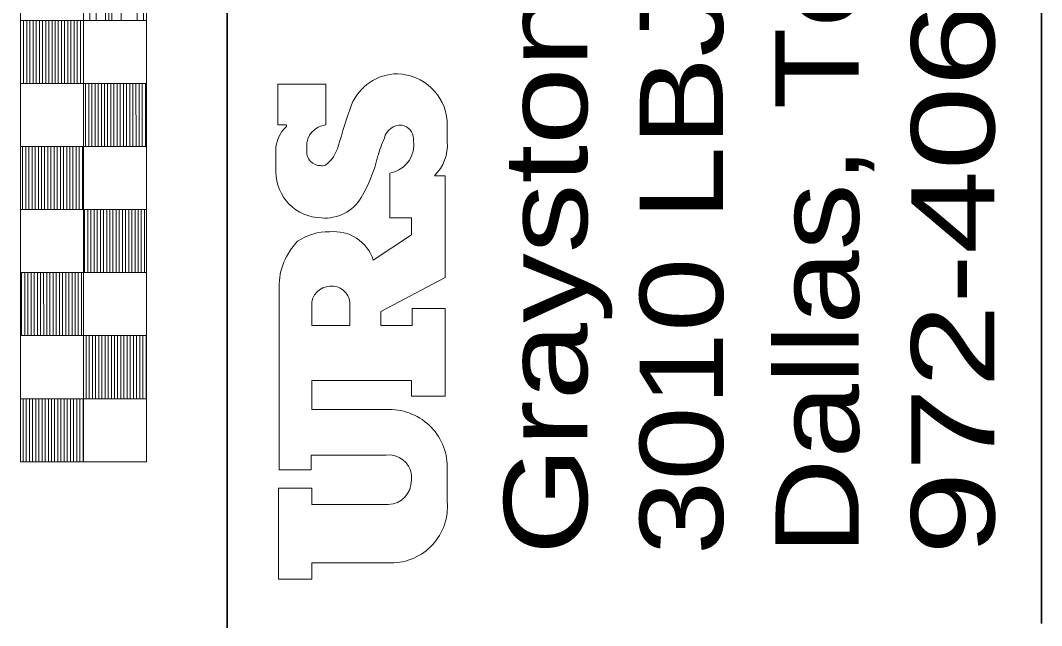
# Model space of a CAD drawing. Extents: x 2363323 to 2367082, y 6956018 to 6980837.
# Drawn here: x 2366568.7 to 2366730.8, y 6979505.4 to 6979601.4 of the extents above; entities that cross this region are included whole.
import ezdxf

# ---------------------------------------------------------------- set-up
doc = ezdxf.new("R2010")
doc.units = 0
doc.header["$LTSCALE"] = 4.1
doc.layers.add('62', color=7, linetype='Continuous', lineweight=13)
doc.layers.add('63', color=7, linetype='Continuous', lineweight=13)

msp = doc.modelspace()

# ---------------------------------------------------------------- linework, layer by layer
at = {"layer": '62', "lineweight": 35}
for p, q in [((2366601.526, 6980156.078), (2366601.527, 6979505.057)), ((2366730.792, 6979899.251), (2366730.792, 6979505.756))]:
    msp.add_line(p, q, dxfattribs=at)
at = {"layer": '62'}
for p, q in [((2366568.707, 6979531.397), (2366568.707, 6979931.434)), ((2366578.708, 6979531.398), (2366578.708, 6979931.434)), ((2366588.708, 6979531.397), (2366588.709, 6979931.434)), ((2366578.719, 6979601.403), (2366578.719, 6979611.405)), ((2366579.719, 6979601.403), (2366579.719, 6979611.406)), ((2366580.719, 6979601.403), (2366580.719, 6979611.405)), ((2366582.219, 6979601.403), (2366582.219, 6979611.406)), ((2366582.719, 6979601.403), (2366582.719, 6979611.405)), ((2366583.219, 6979601.403), (2366583.219, 6979611.405)), ((2366584.719, 6979601.403), (2366584.719, 6979611.406)), ((2366587.219, 6979601.403), (2366587.22, 6979611.406)), ((2366588.22, 6979601.403), (2366588.22, 6979611.405)), ((2366568.719, 6979591.402), (2366568.718, 6979601.404)), ((2366569.219, 6979591.402), (2366569.219, 6979601.404)), ((2366569.721, 6979591.402), (2366569.72, 6979601.403)), ((2366570.221, 6979591.403), (2366570.219, 6979601.403)), ((2366570.72, 6979591.402), (2366570.72, 6979601.403)), ((2366571.22, 6979591.402), (2366571.22, 6979601.404)), ((2366571.719, 6979591.403), (2366571.72, 6979601.403)), ((2366572.22, 6979591.402), (2366572.22, 6979601.403)), ((2366572.72, 6979591.403), (2366572.72, 6979601.404)), ((2366573.22, 6979591.403), (2366573.22, 6979601.403)), ((2366573.72, 6979591.402), (2366573.72, 6979601.404)), ((2366574.219, 6979591.402), (2366574.221, 6979601.404)), ((2366574.72, 6979591.402), (2366574.72, 6979601.403)), ((2366575.22, 6979591.403), (2366575.22, 6979601.403)), ((2366575.72, 6979591.402), (2366575.72, 6979601.403)), ((2366576.22, 6979591.402), (2366576.22, 6979601.404)), ((2366576.72, 6979591.403), (2366576.72, 6979601.403)), ((2366577.22, 6979591.402), (2366577.22, 6979601.403)), ((2366577.72, 6979591.403), (2366577.72, 6979601.404)), ((2366578.22, 6979591.403), (2366578.22, 6979601.403)), ((2366578.707, 6979601.403), (2366588.709, 6979601.404)), ((2366568.707, 6979591.402), (2366578.707, 6979591.402)), ((2366579.05, 6979581.402), (2366579.051, 6979591.403)), ((2366579.551, 6979581.401), (2366579.551, 6979591.403)), ((2366580.05, 6979581.401), (2366580.051, 6979591.404)), ((2366580.55, 6979581.402), (2366580.551, 6979591.403)), ((2366581.051, 6979581.401), (2366581.051, 6979591.404)), ((2366581.55, 6979581.401), (2366581.552, 6979591.403)), ((2366582.051, 6979581.401), (2366582.051, 6979591.402)), ((2366582.551, 6979581.401), (2366582.551, 6979591.403)), ((2366583.05, 6979581.401), (2366583.051, 6979591.403)), ((2366583.551, 6979581.401), (2366583.551, 6979591.403)), ((2366584.051, 6979581.402), (2366584.052, 6979591.403)), ((2366584.551, 6979581.401), (2366584.55, 6979591.403)), ((2366585.051, 6979581.402), (2366585.05, 6979591.404)), ((2366585.551, 6979581.4), (2366585.55, 6979591.403)), ((2366586.052, 6979581.4), (2366586.051, 6979591.403)), ((2366586.552, 6979581.401), (2366586.552, 6979591.403)), ((2366587.052, 6979581.401), (2366587.051, 6979591.403)), ((2366587.552, 6979581.401), (2366587.551, 6979591.404)), ((2366588.053, 6979581.401), (2366588.052, 6979591.403)), ((2366588.552, 6979581.401), (2366588.552, 6979591.404)), ((2366636.462, 6979585.477), (2366636.462, 6979582.143)), ((2366631.133, 6979581.436), (2366631.093, 6979582.636)), ((2366568.706, 6979581.402), (2366578.708, 6979581.401)), ((2366569.049, 6979571.4), (2366569.051, 6979581.401)), ((2366569.55, 6979571.4), (2366569.55, 6979581.401)), ((2366570.051, 6979571.4), (2366570.051, 6979581.401)), ((2366570.551, 6979571.401), (2366570.552, 6979581.401)), ((2366571.051, 6979571.4), (2366571.05, 6979581.401)), ((2366571.551, 6979571.401), (2366571.55, 6979581.402)), ((2366572.051, 6979571.4), (2366572.051, 6979581.402)), ((2366572.551, 6979571.4), (2366572.551, 6979581.402)), ((2366573.051, 6979571.401), (2366573.051, 6979581.402)), ((2366573.551, 6979571.401), (2366573.55, 6979581.401)), ((2366574.051, 6979571.4), (2366574.05, 6979581.402)), ((2366574.551, 6979571.4), (2366574.551, 6979581.401)), ((2366575.051, 6979571.4), (2366575.051, 6979581.402)), ((2366575.551, 6979571.401), (2366575.551, 6979581.401)), ((2366576.051, 6979571.4), (2366576.051, 6979581.401)), ((2366576.551, 6979571.401), (2366576.551, 6979581.402)), ((2366577.051, 6979571.401), (2366577.051, 6979581.402)), ((2366577.55, 6979571.4), (2366577.55, 6979581.401)), ((2366578.05, 6979571.401), (2366578.051, 6979581.401)), ((2366578.55, 6979571.4), (2366578.55, 6979581.401)), ((2366578.707, 6979581.402), (2366588.708, 6979581.401)), ((2366578.708, 6979581.401), (2366588.709, 6979581.402)), ((2366609.239, 6979577.41), (2366609.239, 6979580.744)), ((2366614.165, 6979581.323), (2366614.165, 6979580.638)), ((2366568.707, 6979571.4), (2366578.708, 6979571.4)), ((2366578.895, 6979561.4), (2366578.896, 6979571.4)), ((2366579.395, 6979561.4), (2366579.396, 6979571.4)), ((2366579.896, 6979561.4), (2366579.895, 6979571.4)), ((2366580.395, 6979561.4), (2366580.396, 6979571.4)), ((2366580.896, 6979561.4), (2366580.896, 6979571.4)), ((2366581.396, 6979561.4), (2366581.396, 6979571.4)), ((2366581.895, 6979561.4), (2366581.896, 6979571.4)), ((2366582.396, 6979561.4), (2366582.396, 6979571.4)), ((2366582.895, 6979561.4), (2366582.897, 6979571.401)), ((2366583.396, 6979561.4), (2366583.395, 6979571.4)), ((2366583.896, 6979561.4), (2366583.895, 6979571.4)), ((2366584.396, 6979561.401), (2366584.395, 6979571.4)), ((2366584.896, 6979561.4), (2366584.895, 6979571.4)), ((2366585.396, 6979561.4), (2366585.396, 6979571.401)), ((2366585.897, 6979561.401), (2366585.896, 6979571.401)), ((2366586.396, 6979561.4), (2366586.397, 6979571.4)), ((2366586.896, 6979561.401), (2366586.896, 6979571.4)), ((2366587.396, 6979561.4), (2366587.396, 6979571.4)), ((2366587.896, 6979561.4), (2366587.897, 6979571.4)), ((2366588.397, 6979561.4), (2366588.396, 6979571.4)), ((2366568.706, 6979561.4), (2366578.707, 6979561.401)), ((2366568.895, 6979551.4), (2366568.895, 6979561.401)), ((2366569.395, 6979551.4), (2366569.395, 6979561.4)), ((2366569.897, 6979551.4), (2366569.895, 6979561.401)), ((2366570.396, 6979551.4), (2366570.396, 6979561.4)), ((2366570.897, 6979551.399), (2366570.895, 6979561.4)), ((2366571.396, 6979551.399), (2366571.395, 6979561.4)), ((2366571.896, 6979551.399), (2366571.896, 6979561.401)), ((2366572.396, 6979551.4), (2366572.395, 6979561.401)), ((2366572.895, 6979551.4), (2366572.896, 6979561.4)), ((2366573.395, 6979551.4), (2366573.396, 6979561.401)), ((2366573.896, 6979551.4), (2366573.895, 6979561.401)), ((2366574.395, 6979551.4), (2366574.396, 6979561.401)), ((2366574.896, 6979551.399), (2366574.896, 6979561.401)), ((2366575.395, 6979551.399), (2366575.396, 6979561.4)), ((2366575.895, 6979551.4), (2366575.896, 6979561.4)), ((2366576.396, 6979551.399), (2366576.396, 6979561.4)), ((2366576.895, 6979551.399), (2366576.896, 6979561.401)), ((2366577.396, 6979551.4), (2366577.396, 6979561.4)), ((2366577.896, 6979551.4), (2366577.896, 6979561.4)), ((2366578.396, 6979551.4), (2366578.396, 6979561.401)), ((2366578.707, 6979561.4), (2366588.709, 6979561.4)), ((2366578.708, 6979561.398), (2366588.709, 6979561.398)), ((2366614.942, 6979552.995), (2366614.942, 6979556.76)), ((2366568.707, 6979551.399), (2366578.707, 6979551.399)), ((2366579.14, 6979541.398), (2366579.14, 6979551.398)), ((2366579.64, 6979541.398), (2366579.64, 6979551.397)), ((2366580.14, 6979541.398), (2366580.141, 6979551.398)), ((2366580.64, 6979541.398), (2366580.64, 6979551.398)), ((2366581.14, 6979541.398), (2366581.14, 6979551.399)), ((2366581.64, 6979541.399), (2366581.641, 6979551.398)), ((2366582.14, 6979541.397), (2366582.14, 6979551.398)), ((2366582.64, 6979541.398), (2366582.641, 6979551.397)), ((2366583.14, 6979541.398), (2366583.14, 6979551.397)), ((2366583.64, 6979541.397), (2366583.64, 6979551.398)), ((2366584.14, 6979541.398), (2366584.141, 6979551.398)), ((2366584.641, 6979541.398), (2366584.64, 6979551.397)), ((2366585.141, 6979541.398), (2366585.141, 6979551.398)), ((2366585.642, 6979541.398), (2366585.642, 6979551.398)), ((2366586.141, 6979541.397), (2366586.142, 6979551.399)), ((2366586.641, 6979541.398), (2366586.642, 6979551.397)), ((2366587.142, 6979541.397), (2366587.142, 6979551.398)), ((2366587.642, 6979541.398), (2366587.641, 6979551.398)), ((2366588.142, 6979541.397), (2366588.141, 6979551.398)), ((2366588.642, 6979541.397), (2366588.641, 6979551.399)), ((2366568.708, 6979541.398), (2366578.708, 6979541.398)), ((2366569.138, 6979531.397), (2366569.14, 6979541.399)), ((2366569.64, 6979531.398), (2366569.64, 6979541.399)), ((2366570.14, 6979531.397), (2366570.14, 6979541.399)), ((2366570.64, 6979531.398), (2366570.64, 6979541.398)), ((2366571.14, 6979531.397), (2366571.14, 6979541.398)), ((2366571.64, 6979531.398), (2366571.64, 6979541.398)), ((2366572.14, 6979531.397), (2366572.14, 6979541.398)), ((2366572.64, 6979531.397), (2366572.64, 6979541.399)), ((2366573.14, 6979531.398), (2366573.14, 6979541.398)), ((2366573.64, 6979531.397), (2366573.64, 6979541.398)), ((2366574.14, 6979531.397), (2366574.14, 6979541.398)), ((2366574.64, 6979531.397), (2366574.639, 6979541.398)), ((2366575.14, 6979531.397), (2366575.139, 6979541.399)), ((2366575.64, 6979531.398), (2366575.639, 6979541.398)), ((2366576.14, 6979531.397), (2366576.139, 6979541.399)), ((2366576.64, 6979531.398), (2366576.64, 6979541.399)), ((2366577.14, 6979531.398), (2366577.139, 6979541.399)), ((2366577.639, 6979531.397), (2366577.64, 6979541.399)), ((2366578.139, 6979531.397), (2366578.139, 6979541.398)), ((2366578.639, 6979531.397), (2366578.639, 6979541.399)), ((2366578.708, 6979541.398), (2366588.709, 6979541.398)), ((2366568.707, 6979531.397), (2366578.708, 6979531.398)), ((2366636.466, 6979530.582), (2366636.462, 6979525.031)), ((2366630.759, 6979528.473), (2366630.759, 6979529.333))]:
    msp.add_line(p, q, dxfattribs=at)
for points in [[(2366588.71, 6979591.403), (2366588.709, 6979601.404), (2366568.707, 6979601.404), (2366568.707, 6979591.402)], [(2366588.709, 6979571.401), (2366588.709, 6979581.402), (2366568.706, 6979581.402), (2366568.707, 6979571.4)], [(2366588.709, 6979551.399), (2366588.709, 6979561.4), (2366568.706, 6979561.4), (2366568.707, 6979551.399)], [(2366588.708, 6979531.397), (2366588.709, 6979541.398), (2366568.708, 6979541.398), (2366568.707, 6979531.397)]]:
    msp.add_lwpolyline(points, close=True, dxfattribs=at)
for points in [[(2366610.926, 6979584.59), (2366610.926, 6979584.832), (2366609.561, 6979584.832), (2366609.561, 6979591.285), (2366617.201, 6979591.285), (2366617.201, 6979584.832)], [(2366624.713, 6979563.379), (2366630.759, 6979567.408), (2366630.759, 6979570.096), (2366627.316, 6979570.096), (2366627.316, 6979577.195)], [(2366634.418, 6979576.765), (2366636.14, 6979576.765), (2366636.14, 6979560.632), (2366625.917, 6979555.254), (2366625.917, 6979552.995), (2366630.867, 6979552.995), (2366630.867, 6979555.684), (2366636.14, 6979555.684), (2366636.14, 6979541.809), (2366630.759, 6979541.809), (2366630.759, 6979544.283), (2366614.942, 6979544.283), (2366614.942, 6979539.658), (2366626.778, 6979539.658)], [(2366626.778, 6979532.452), (2366614.834, 6979532.452), (2366614.834, 6979530.086), (2366609.777, 6979530.086), (2366609.777, 6979559.126)], [(2366620.967, 6979556.114), (2366620.967, 6979552.995), (2366614.942, 6979552.995)], [(2366627.531, 6979515.351), (2366614.942, 6979515.351), (2366614.942, 6979512.769), (2366609.669, 6979512.769), (2366609.669, 6979527.182), (2366614.942, 6979527.182), (2366614.942, 6979524.601), (2366627.101, 6979524.601)]]:
    msp.add_lwpolyline(points, dxfattribs=at)
for centre, radius, start, end in [((2366628.637, 6979584.927), 8.011, 90.4748, 157.35647), ((2366628.279, 6979584.726), 8.217, 5.23994, 87.97211), ((2366787.718, 6979531.062), 175.947, 161.11463, 163.35109), ((2366614.436, 6979580.757), 5.197, 132.47521, 180.13887), ((2366617.49, 6979581.513), 3.331, 94.97622, 183.26328), ((2366629.068, 6979582.123), 2.67, 86.42761, 166.58817), ((2366628.848, 6979582.575), 2.246, 1.56527, 80.09036), ((2366651.95, 6979571.919), 27.683, 156.98519, 163.48674), ((2366629.671, 6979581.647), 6.809, 314.19553, 4.1738), ((2366616.33, 6979580.533), 2.168, 177.22466, 270.15025), ((2366613.919, 6979582.788), 5.391, 306.33025, 345.86761), ((2366626.654, 6979581.629), 4.484, 278.49107, 357.52171), ((2366603.504, 6979584.874), 22.488, 329.02736, 346.92656), ((2366616.608, 6979577.452), 7.37, 180.32724, 269.1529), ((2366616.559, 6979580.015), 1.665, 262.3102, 289.43935), ((2366617.121, 6979576.617), 6.564, 264.56461, 329.65547), ((2366617.465, 6979559.565), 8.298, 87.96198, 124.96984), ((2366618.527, 6979561.413), 6.491, 17.63424, 96.78306), ((2366619.969, 6979559.211), 10.193, 135.41811, 180.47644), ((2366617.98, 6979556.159), 3.097, 81.97357, 168.82266), ((2366618.149, 6979556.405), 2.833, 354.11318, 84.67155), ((2366627.315, 6979530.523), 9.151, 0.37291, 93.36394), ((2366627.197, 6979528.886), 3.591, 7.15138, 96.69605), ((2366626.953, 6979528.405), 3.807, 272.2293, 1.01817), ((2366627.54, 6979524.303), 8.952, 269.94292, 4.66557)]:
    msp.add_arc(centre, radius, start, end, dxfattribs=at)
at = {"layer": '63'}
for p, q in [((2366568.707, 6979531.397), (2366568.707, 6979931.434)), ((2366578.708, 6979531.398), (2366578.708, 6979931.434)), ((2366588.708, 6979531.397), (2366588.709, 6979931.434)), ((2366578.719, 6979601.403), (2366578.719, 6979611.405)), ((2366579.719, 6979601.403), (2366579.719, 6979611.406)), ((2366580.719, 6979601.403), (2366580.719, 6979611.405)), ((2366582.219, 6979601.403), (2366582.219, 6979611.406)), ((2366582.719, 6979601.403), (2366582.719, 6979611.405)), ((2366583.219, 6979601.403), (2366583.219, 6979611.405)), ((2366584.719, 6979601.403), (2366584.719, 6979611.406)), ((2366587.219, 6979601.403), (2366587.22, 6979611.406)), ((2366588.22, 6979601.403), (2366588.22, 6979611.405)), ((2366568.719, 6979591.402), (2366568.718, 6979601.404)), ((2366569.219, 6979591.402), (2366569.219, 6979601.404)), ((2366569.721, 6979591.402), (2366569.72, 6979601.403)), ((2366570.221, 6979591.403), (2366570.219, 6979601.403)), ((2366570.72, 6979591.402), (2366570.72, 6979601.403)), ((2366571.22, 6979591.402), (2366571.22, 6979601.404)), ((2366571.719, 6979591.403), (2366571.72, 6979601.403)), ((2366572.22, 6979591.402), (2366572.22, 6979601.403)), ((2366572.72, 6979591.403), (2366572.72, 6979601.404)), ((2366573.22, 6979591.403), (2366573.22, 6979601.403)), ((2366573.72, 6979591.402), (2366573.72, 6979601.404)), ((2366574.219, 6979591.402), (2366574.221, 6979601.404)), ((2366574.72, 6979591.402), (2366574.72, 6979601.403)), ((2366575.22, 6979591.403), (2366575.22, 6979601.403)), ((2366575.72, 6979591.402), (2366575.72, 6979601.403)), ((2366576.22, 6979591.402), (2366576.22, 6979601.404)), ((2366576.72, 6979591.403), (2366576.72, 6979601.403)), ((2366577.22, 6979591.402), (2366577.22, 6979601.403)), ((2366577.72, 6979591.403), (2366577.72, 6979601.404)), ((2366578.22, 6979591.403), (2366578.22, 6979601.403)), ((2366578.707, 6979601.403), (2366588.709, 6979601.404)), ((2366568.707, 6979591.402), (2366578.707, 6979591.402)), ((2366579.05, 6979581.402), (2366579.051, 6979591.403)), ((2366579.551, 6979581.401), (2366579.551, 6979591.403)), ((2366580.05, 6979581.401), (2366580.051, 6979591.404)), ((2366580.55, 6979581.402), (2366580.551, 6979591.403)), ((2366581.051, 6979581.401), (2366581.051, 6979591.404)), ((2366581.55, 6979581.401), (2366581.552, 6979591.403)), ((2366582.051, 6979581.401), (2366582.051, 6979591.402)), ((2366582.551, 6979581.401), (2366582.551, 6979591.403)), ((2366583.05, 6979581.401), (2366583.051, 6979591.403)), ((2366583.551, 6979581.401), (2366583.551, 6979591.403)), ((2366584.051, 6979581.402), (2366584.052, 6979591.403)), ((2366584.551, 6979581.401), (2366584.55, 6979591.403)), ((2366585.051, 6979581.402), (2366585.05, 6979591.404)), ((2366585.551, 6979581.4), (2366585.55, 6979591.403)), ((2366586.052, 6979581.4), (2366586.051, 6979591.403)), ((2366586.552, 6979581.401), (2366586.552, 6979591.403)), ((2366587.052, 6979581.401), (2366587.051, 6979591.403)), ((2366587.552, 6979581.401), (2366587.551, 6979591.404)), ((2366588.053, 6979581.401), (2366588.052, 6979591.403)), ((2366588.552, 6979581.401), (2366588.552, 6979591.404)), ((2366568.706, 6979581.402), (2366578.708, 6979581.401)), ((2366569.049, 6979571.4), (2366569.051, 6979581.401)), ((2366569.55, 6979571.4), (2366569.55, 6979581.401)), ((2366570.051, 6979571.4), (2366570.051, 6979581.401)), ((2366570.551, 6979571.401), (2366570.552, 6979581.401)), ((2366571.051, 6979571.4), (2366571.05, 6979581.401)), ((2366571.551, 6979571.401), (2366571.55, 6979581.402)), ((2366572.051, 6979571.4), (2366572.051, 6979581.402)), ((2366572.551, 6979571.4), (2366572.551, 6979581.402)), ((2366573.051, 6979571.401), (2366573.051, 6979581.402)), ((2366573.551, 6979571.401), (2366573.55, 6979581.401)), ((2366574.051, 6979571.4), (2366574.05, 6979581.402)), ((2366574.551, 6979571.4), (2366574.551, 6979581.401)), ((2366575.051, 6979571.4), (2366575.051, 6979581.402)), ((2366575.551, 6979571.401), (2366575.551, 6979581.401)), ((2366576.051, 6979571.4), (2366576.051, 6979581.401)), ((2366576.551, 6979571.401), (2366576.551, 6979581.402)), ((2366577.051, 6979571.401), (2366577.051, 6979581.402)), ((2366577.55, 6979571.4), (2366577.55, 6979581.401)), ((2366578.05, 6979571.401), (2366578.051, 6979581.401)), ((2366578.55, 6979571.4), (2366578.55, 6979581.401)), ((2366578.707, 6979581.402), (2366588.708, 6979581.401)), ((2366578.708, 6979581.401), (2366588.709, 6979581.402)), ((2366568.707, 6979571.4), (2366578.708, 6979571.4)), ((2366578.895, 6979561.4), (2366578.896, 6979571.4)), ((2366579.395, 6979561.4), (2366579.396, 6979571.4)), ((2366579.896, 6979561.4), (2366579.895, 6979571.4)), ((2366580.395, 6979561.4), (2366580.396, 6979571.4)), ((2366580.896, 6979561.4), (2366580.896, 6979571.4)), ((2366581.396, 6979561.4), (2366581.396, 6979571.4)), ((2366581.895, 6979561.4), (2366581.896, 6979571.4)), ((2366582.396, 6979561.4), (2366582.396, 6979571.4)), ((2366582.895, 6979561.4), (2366582.897, 6979571.401)), ((2366583.396, 6979561.4), (2366583.395, 6979571.4)), ((2366583.896, 6979561.4), (2366583.895, 6979571.4)), ((2366584.396, 6979561.401), (2366584.395, 6979571.4)), ((2366584.896, 6979561.4), (2366584.895, 6979571.4)), ((2366585.396, 6979561.4), (2366585.396, 6979571.401)), ((2366585.897, 6979561.401), (2366585.896, 6979571.401)), ((2366586.396, 6979561.4), (2366586.397, 6979571.4)), ((2366586.896, 6979561.401), (2366586.896, 6979571.4)), ((2366587.396, 6979561.4), (2366587.396, 6979571.4)), ((2366587.896, 6979561.4), (2366587.897, 6979571.4)), ((2366588.397, 6979561.4), (2366588.396, 6979571.4)), ((2366568.706, 6979561.4), (2366578.707, 6979561.401)), ((2366568.895, 6979551.4), (2366568.895, 6979561.401)), ((2366569.395, 6979551.4), (2366569.395, 6979561.4)), ((2366569.897, 6979551.4), (2366569.895, 6979561.401)), ((2366570.396, 6979551.4), (2366570.396, 6979561.4)), ((2366570.897, 6979551.399), (2366570.895, 6979561.4)), ((2366571.396, 6979551.399), (2366571.395, 6979561.4)), ((2366571.896, 6979551.399), (2366571.896, 6979561.401)), ((2366572.396, 6979551.4), (2366572.395, 6979561.401)), ((2366572.895, 6979551.4), (2366572.896, 6979561.4)), ((2366573.395, 6979551.4), (2366573.396, 6979561.401)), ((2366573.896, 6979551.4), (2366573.895, 6979561.401)), ((2366574.395, 6979551.4), (2366574.396, 6979561.401)), ((2366574.896, 6979551.399), (2366574.896, 6979561.401)), ((2366575.395, 6979551.399), (2366575.396, 6979561.4)), ((2366575.895, 6979551.4), (2366575.896, 6979561.4)), ((2366576.396, 6979551.399), (2366576.396, 6979561.4)), ((2366576.895, 6979551.399), (2366576.896, 6979561.401)), ((2366577.396, 6979551.4), (2366577.396, 6979561.4)), ((2366577.896, 6979551.4), (2366577.896, 6979561.4)), ((2366578.396, 6979551.4), (2366578.396, 6979561.401)), ((2366578.707, 6979561.4), (2366588.709, 6979561.4)), ((2366578.708, 6979561.398), (2366588.709, 6979561.398)), ((2366568.707, 6979551.399), (2366578.707, 6979551.399)), ((2366579.14, 6979541.398), (2366579.14, 6979551.398)), ((2366579.64, 6979541.398), (2366579.64, 6979551.397)), ((2366580.14, 6979541.398), (2366580.141, 6979551.398)), ((2366580.64, 6979541.398), (2366580.64, 6979551.398)), ((2366581.14, 6979541.398), (2366581.14, 6979551.399)), ((2366581.64, 6979541.399), (2366581.641, 6979551.398)), ((2366582.14, 6979541.397), (2366582.14, 6979551.398)), ((2366582.64, 6979541.398), (2366582.641, 6979551.397)), ((2366583.14, 6979541.398), (2366583.14, 6979551.397)), ((2366583.64, 6979541.397), (2366583.64, 6979551.398)), ((2366584.14, 6979541.398), (2366584.141, 6979551.398)), ((2366584.641, 6979541.398), (2366584.64, 6979551.397)), ((2366585.141, 6979541.398), (2366585.141, 6979551.398)), ((2366585.642, 6979541.398), (2366585.642, 6979551.398)), ((2366586.141, 6979541.397), (2366586.142, 6979551.399)), ((2366586.641, 6979541.398), (2366586.642, 6979551.397)), ((2366587.142, 6979541.397), (2366587.142, 6979551.398)), ((2366587.642, 6979541.398), (2366587.641, 6979551.398)), ((2366588.142, 6979541.397), (2366588.141, 6979551.398)), ((2366588.642, 6979541.397), (2366588.641, 6979551.399)), ((2366568.708, 6979541.398), (2366578.708, 6979541.398)), ((2366569.138, 6979531.397), (2366569.14, 6979541.399)), ((2366569.64, 6979531.398), (2366569.64, 6979541.399)), ((2366570.14, 6979531.397), (2366570.14, 6979541.399)), ((2366570.64, 6979531.398), (2366570.64, 6979541.398)), ((2366571.14, 6979531.397), (2366571.14, 6979541.398)), ((2366571.64, 6979531.398), (2366571.64, 6979541.398)), ((2366572.14, 6979531.397), (2366572.14, 6979541.398)), ((2366572.64, 6979531.397), (2366572.64, 6979541.399)), ((2366573.14, 6979531.398), (2366573.14, 6979541.398)), ((2366573.64, 6979531.397), (2366573.64, 6979541.398)), ((2366574.14, 6979531.397), (2366574.14, 6979541.398)), ((2366574.64, 6979531.397), (2366574.639, 6979541.398)), ((2366575.14, 6979531.397), (2366575.139, 6979541.399)), ((2366575.64, 6979531.398), (2366575.639, 6979541.398)), ((2366576.14, 6979531.397), (2366576.139, 6979541.399)), ((2366576.64, 6979531.398), (2366576.64, 6979541.399)), ((2366577.14, 6979531.398), (2366577.139, 6979541.399)), ((2366577.639, 6979531.397), (2366577.64, 6979541.399)), ((2366578.139, 6979531.397), (2366578.139, 6979541.398)), ((2366578.639, 6979531.397), (2366578.639, 6979541.399)), ((2366578.708, 6979541.398), (2366588.709, 6979541.398)), ((2366568.707, 6979531.397), (2366578.708, 6979531.398))]:
    msp.add_line(p, q, dxfattribs=at)
for points in [[(2366588.71, 6979591.403), (2366588.709, 6979601.404), (2366568.707, 6979601.404), (2366568.707, 6979591.402)], [(2366588.709, 6979571.401), (2366588.709, 6979581.402), (2366568.706, 6979581.402), (2366568.707, 6979571.4)], [(2366588.709, 6979551.399), (2366588.709, 6979561.4), (2366568.706, 6979561.4), (2366568.707, 6979551.399)], [(2366588.708, 6979531.397), (2366588.709, 6979541.398), (2366568.708, 6979541.398), (2366568.707, 6979531.397)]]:
    msp.add_lwpolyline(points, close=True, dxfattribs=at)

# ---------------------------------------------------------------- texts
at = {"layer": '62'}
for s, width, p in [('3010 LBJ Freeway, Suite 1300', 1.2, (2366680.223, 6979516.586)), ('Dallas, Texas 75234', 1.2, (2366701.77, 6979516.586)), ('Graystone Centre', 1.25, (2366658.675, 6979516.586)), ('972-406-6950', 1.35, (2366723.318, 6979516.586))]:
    msp.add_text(s, height=13.22, rotation=90, dxfattribs=dict(at, width=width)).set_placement(p)

doc.saveas('drawing.dxf')
